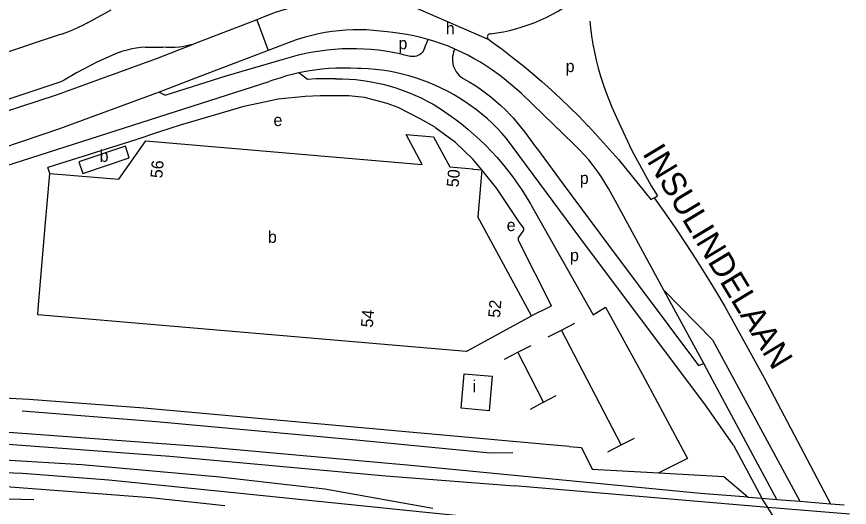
# Model space of a CAD drawing. Extents: x 161494 to 163033, y 383688 to 384862.
# Drawn here: x 162712.5 to 162990.6, y 384018.3 to 384182.1 of the extents above; entities that cross this region are included whole.
import ezdxf

# ---------------------------------------------------------------- set-up
doc = ezdxf.new("R2010")
doc.units = 0
for name, color, linetype in [('BLT_Basislijn', 7, 'Continuous'), ('BLT_Bebouwing', 7, 'Continuous'), ('BLT_Centroide', 7, 'Continuous'), ('BLT_Huisnummer_reeks', 7, 'Continuous'), ('BLT_Spoorlijn', 7, 'Continuous'), ('BLT_Straatnaam_hoofdweg', 7, 'Continuous'), ('BLT_Vlakafsluiter', 7, 'Continuous')]:
    doc.layers.add(name, color=color, linetype=linetype)

msp = doc.modelspace()

# ---------------------------------------------------------------- linework, layer by layer
at = {"layer": 'BLT_Basislijn'}
for p, q in [((162736.15, 384180.03), (162744.08, 384184.32)), ((162792.67, 384181), (162771.29, 384172.75)), ((162727.04, 384176.07), (162682.21, 384161.19)), ((162848.71, 384171.58), (162849.96, 384174.45)), ((162870.21, 384174.43), (162871.16, 384173.7)), ((162755.54, 384171.89), (162761.33, 384171.89)), ((162858.44, 384170.24), (162858.85, 384171.26)), ((162725.87, 384155.94), (162759.59, 384168.21)), ((162841.62, 384169.48), (162843.9, 384168.84)), ((162686.99, 384125.31), (162796.88, 384160.38)), ((162717.96, 384157.23), (162715.59, 384156.44)), ((162760.23, 384143.65), (162752.33, 384140.98)), ((162900.62, 384108.34), (162876.11, 384141.44)), ((162886.41, 384137.8), (162895.04, 384126.21)), ((162723.59, 384129.76), (162722.91, 384131.71)), ((162895.04, 384126.21), (162910.16, 384105.82)), ((162928.62, 384090.76), (162912.35, 384120.67)), ((162924.23, 384121.01), (162925.4, 384121.63)), ((162925.4, 384121.63), (162926.54, 384122.24)), ((162941.97, 384066.24), (162928.62, 384090.76)), ((162894.47, 384077.46), (162898.93, 384079.78)), ((162890, 384075.14), (162894.47, 384077.46)), ((162914.4, 384039.1), (162894.47, 384077.46)), ((162944.9, 384074.22), (162974.05, 384020.29)), ((162875.38, 384067.71), (162879.85, 384070.03)), ((162879.85, 384070.03), (162884.32, 384072.35)), ((162888.49, 384053.4), (162879.85, 384070.03)), ((162944.9, 384060.86), (162941.97, 384066.24)), ((162921.5, 384062.58), (162936.56, 384034.59)), ((162966.31, 384020.93), (162944.9, 384060.86)), ((162962.07, 384061.51), (162984.26, 384019.45)), ((162716.59, 384054.27), (162692.1, 384055.57)), ((162888.49, 384053.4), (162884.03, 384050.89)), ((162888.49, 384053.4), (162892.68, 384055.66)), ((162914.4, 384039.1), (162918.87, 384041.42)), ((162909.93, 384036.78), (162914.4, 384039.1)), ((162951.9, 384039), (162961.39, 384021.34)), ((162936.56, 384034.59), (162926.96, 384029.78)), ((162926.96, 384029.78), (162948.64, 384028.55)), ((162948.64, 384028.55), (162956.78, 384021.72)), ((162956.78, 384021.72), (162961.39, 384021.34)), ((162961.39, 384021.34), (162966.31, 384020.93)), ((162966.31, 384020.93), (162974.05, 384020.29)), ((162974.05, 384020.29), (162984.26, 384019.45)), ((162984.26, 384019.45), (162988.85, 384019.07))]:
    msp.add_line(p, q, dxfattribs=at)
for points in [[(162831.29, 384188.57), (162830.8, 384188.59), (162828.09, 384188.59), (162825.38, 384188.52), (162822.67, 384188.36), (162819.97, 384188.13), (162817.27, 384187.81), (162814.59, 384187.42), (162811.92, 384186.94), (162809.26, 384186.39), (162806.62, 384185.76), (162804, 384185.06), (162801.4, 384184.27), (162798.83, 384183.41), (162796.28, 384182.48), (162793.77, 384181.47), (162792.71, 384181.02)], [(162870.78, 384176.39), (162872.91, 384176.68), (162875.03, 384177.05), (162877.14, 384177.5), (162879.23, 384178.02), (162881.3, 384178.63), (162883.34, 384179.3), (162885.35, 384180.06), (162887.34, 384180.89), (162889.3, 384181.79), (162891.21, 384182.77), (162893.1, 384183.81), (162894.94, 384184.93), (162896.74, 384186.11), (162898.49, 384187.35), (162899.83, 384188.38)], [(162736.15, 384180.03), (162734.54, 384179.14), (162732.88, 384178.32), (162731.2, 384177.56), (162729.48, 384176.89), (162727.73, 384176.28), (162727.04, 384176.07)], [(162792.71, 384181.02), (162792.67, 384181)], [(162903.87, 384180.62), (162904.11, 384178.34), (162904.48, 384175.61), (162904.92, 384172.89), (162905.45, 384170.19), (162906.05, 384167.51), (162906.73, 384164.84), (162907.49, 384162.19), (162908.33, 384159.57), (162909.24, 384156.97), (162910.22, 384154.4), (162911.28, 384151.86), (162912.42, 384149.36), (162912.84, 384148.46)], [(162836.24, 384176.99), (162833.95, 384177.28), (162831.66, 384177.49), (162829.36, 384177.62), (162827.06, 384177.67), (162824.75, 384177.65), (162822.45, 384177.54), (162820.16, 384177.35), (162817.87, 384177.08), (162815.59, 384176.74), (162813.33, 384176.31), (162811.08, 384175.8), (162808.85, 384175.22), (162806.64, 384174.56), (162805.85, 384174.31)], [(162849.96, 384174.45), (162849.85, 384174.49), (162847.53, 384175.11), (162845.19, 384175.65), (162842.84, 384176.11), (162840.47, 384176.5), (162838.09, 384176.8), (162836.24, 384176.99)], [(162870.78, 384176.39), (162870.49, 384176.36), (162870.22, 384176.26), (162869.99, 384176.09), (162869.82, 384175.86), (162869.71, 384175.59), (162869.68, 384175.3), (162869.73, 384175.02), (162869.86, 384174.76), (162870.05, 384174.54), (162870.21, 384174.43)], [(162805.85, 384174.31), (162796.52, 384170.75)], [(162858.85, 384171.26), (162856.67, 384172.17), (162854.42, 384173.02), (162852.15, 384173.79), (162849.96, 384174.45)], [(162871.16, 384173.7), (162874.59, 384171.18), (162877.98, 384168.6), (162881.31, 384165.95), (162884.6, 384163.24), (162887.83, 384160.47), (162891.01, 384157.64), (162894.14, 384154.75), (162897.21, 384151.8), (162900.23, 384148.8), (162903.18, 384145.73), (162903.44, 384145.47)], [(162755.54, 384171.89), (162753.99, 384171.77), (162752.46, 384171.57), (162750.93, 384171.29), (162749.42, 384170.93), (162747.93, 384170.5), (162746.46, 384169.99), (162745.58, 384169.64)], [(162796.47, 384170.74), (162789.5, 384168.08), (162773.74, 384162.08), (162760.16, 384156.84)], [(162771.29, 384172.75), (162769.84, 384172.39), (162768.37, 384172.12), (162766.89, 384171.92), (162765.4, 384171.8), (162763.9, 384171.77), (162762.41, 384171.81), (162761.33, 384171.89)], [(162796.52, 384170.75), (162796.47, 384170.74)], [(162801.93, 384167.98), (162804.27, 384168.68), (162806.63, 384169.3), (162809.01, 384169.85), (162811.41, 384170.32), (162813.82, 384170.71), (162816.24, 384171.02), (162818.67, 384171.25), (162821.11, 384171.4), (162823.55, 384171.47), (162825.99, 384171.46), (162828.43, 384171.37), (162830.86, 384171.2), (162833.29, 384170.95), (162835.71, 384170.62), (162838.12, 384170.22), (162840.51, 384169.73), (162841.62, 384169.48)], [(162848.71, 384171.58), (162848.51, 384171.05), (162848.23, 384170.56), (162847.88, 384170.1), (162847.47, 384169.7), (162847.02, 384169.36), (162846.52, 384169.09), (162845.98, 384168.89), (162845.43, 384168.77), (162844.86, 384168.73), (162844.29, 384168.77), (162843.9, 384168.84)], [(162858.44, 384170.24), (162858.23, 384169.5), (162858.09, 384168.75), (162858.03, 384167.98), (162858.05, 384167.22), (162858.15, 384166.45), (162858.33, 384165.71), (162858.59, 384164.98), (162858.92, 384164.29), (162859.32, 384163.63), (162859.78, 384163.02), (162860.31, 384162.46), (162860.89, 384161.96), (162861.52, 384161.53), (162861.67, 384161.44)], [(162875.26, 384161.33), (162873.36, 384162.8), (162871.42, 384164.21), (162869.43, 384165.56), (162867.4, 384166.83), (162865.33, 384168.04), (162863.21, 384169.18), (162861.07, 384170.25), (162858.85, 384171.26)], [(162745.58, 384169.64), (162739.31, 384166.87), (162732.56, 384163.34), (162728.38, 384160.87), (162727.31, 384160.33), (162717.96, 384157.23)], [(162760.16, 384156.84), (162762.06, 384155.86), (162782.53, 384162.29), (162801.93, 384167.98)], [(162826.31, 384164.8), (162823.92, 384164.9), (162821.53, 384164.93), (162819.14, 384164.88), (162816.76, 384164.74), (162814.37, 384164.53), (162812, 384164.23), (162809.64, 384163.86), (162807.29, 384163.41), (162806.69, 384163.27)], [(162876.11, 384141.44), (162874.58, 384143.17), (162872.99, 384144.85), (162871.34, 384146.47), (162869.64, 384148.03), (162867.89, 384149.53), (162866.08, 384150.97), (162864.23, 384152.35), (162862.33, 384153.66), (162860.38, 384154.9), (162858.4, 384156.08), (162856.37, 384157.19), (162854.31, 384158.22), (162852.21, 384159.19), (162850.08, 384160.08), (162847.92, 384160.9), (162845.73, 384161.64), (162843.52, 384162.3), (162841.29, 384162.89), (162839.04, 384163.4), (162836.77, 384163.83), (162834.49, 384164.19), (162832.19, 384164.46), (162829.89, 384164.66), (162827.59, 384164.77), (162826.31, 384164.8)], [(162806.69, 384163.27), (162804.96, 384162.88), (162802.65, 384162.27), (162800.36, 384161.59), (162798.09, 384160.83), (162796.88, 384160.38)], [(162819.02, 384161.37), (162812.44, 384161.35), (162809.65, 384161.13), (162806.69, 384163.27)], [(162819.02, 384161.37), (162821.29, 384161.35), (162823.56, 384161.24), (162825.82, 384161.06), (162828.07, 384160.79), (162830.31, 384160.45), (162832.54, 384160.03), (162834.76, 384159.53), (162836.95, 384158.95), (162839.12, 384158.3), (162841.27, 384157.57), (162843.39, 384156.76), (162845.49, 384155.88), (162847.54, 384154.93), (162849.57, 384153.9), (162851.56, 384152.81), (162853.5, 384151.64), (162854.38, 384151.08)], [(162861.67, 384161.44), (162863.6, 384160.34), (162865.48, 384159.18), (162867.33, 384157.95), (162869.12, 384156.66), (162870.87, 384155.3), (162872.57, 384153.88), (162874.22, 384152.4), (162875.81, 384150.86), (162877.34, 384149.26), (162878.26, 384148.25)], [(162898.57, 384139.54), (162888.34, 384149.42), (162880.94, 384156.5), (162875.26, 384161.33)], [(162715.59, 384156.44), (162687.56, 384147.15), (162682.63, 384142.96)], [(162760.16, 384156.84), (162726.82, 384144.61), (162688.65, 384131.73)], [(162867.84, 384130.92), (162867.27, 384131.62), (162864.82, 384134.51), (162859, 384140.05), (162852.51, 384144.86), (162852.03, 384145.24), (162847.27, 384147.95), (162839.9, 384151.78), (162836.27, 384153.08), (162828.7, 384155.04), (162823.44, 384155.6), (162813.84, 384155.63), (162808.83, 384155.38), (162799.89, 384154.49), (162795.23, 384153.54), (162788.34, 384152.1), (162767.17, 384145.89), (162760.23, 384143.65)], [(162854.38, 384151.08), (162856.64, 384149.55), (162858.86, 384147.95), (162861.03, 384146.29), (162863.15, 384144.57), (162865.21, 384142.78), (162867.23, 384140.94), (162869.18, 384139.03), (162871.09, 384137.07), (162872.93, 384135.06), (162874.71, 384132.99), (162876.43, 384130.87), (162878.1, 384128.7), (162879.69, 384126.49), (162881.22, 384124.22), (162882.68, 384121.92), (162884.08, 384119.57), (162884.29, 384119.2)], [(162878.26, 384148.25), (162880.24, 384145.92), (162882.17, 384143.55), (162884.02, 384141.12), (162885.82, 384138.65), (162886.41, 384137.8)], [(162912.84, 384148.46), (162917.97, 384137.34), (162924.38, 384125.58), (162926.54, 384122.24)], [(162903.44, 384145.47), (162913.48, 384134.35), (162924.23, 384121.01)], [(162752.33, 384140.98), (162722.91, 384131.71)], [(162912.35, 384120.67), (162911.29, 384122.73), (162910.17, 384124.76), (162908.97, 384126.74), (162907.71, 384128.68), (162906.38, 384130.58), (162904.99, 384132.43), (162903.53, 384134.23), (162902.02, 384135.98), (162900.44, 384137.67), (162898.8, 384139.32), (162898.57, 384139.54)], [(162891.13, 384085.57), (162880.1, 384107.36), (162880.04, 384108.25), (162881.92, 384110.8), (162881.92, 384111.49), (162880.42, 384113.34), (162872.85, 384124.72), (162867.84, 384130.92)], [(162925.4, 384121.63), (162928.97, 384116.56), (162932.48, 384111.45), (162935.93, 384106.28), (162939.31, 384101.08), (162942.62, 384095.83), (162945.86, 384090.54), (162948.97, 384085.3)], [(162884.29, 384119.2), (162904.99, 384082.54), (162909.18, 384085.08), (162921.5, 384062.58)], [(162951.9, 384039), (162942.86, 384051.91), (162900.62, 384108.34)], [(162910.16, 384105.82), (162940.18, 384065.64), (162941.97, 384066.24)], [(162891.13, 384085.57), (162890.3, 384085.14), (162884.46, 384082.15)], [(162896.99, 384038.57), (162888.11, 384039.33), (162754.96, 384051.37), (162716.59, 384054.27)], [(162714.37, 384050.52), (162759.19, 384046.91), (162823.65, 384041.08), (162870.58, 384036.51), (162878.21, 384036.64)], [(162956.78, 384021.72), (162940.81, 384022.86), (162844.13, 384032.25), (162776, 384038.39), (162705.31, 384043.59), (162655, 384044.9), (162627.45, 384044.8), (162579.26, 384042.49), (162510.26, 384034.87), (162452.51, 384024.7), (162377.46, 384008.85), (162301.58, 383991.65), (162233.15, 383976.81), (162161.35, 383961.08), (162082.65, 383946.35), (162000.1, 383931.74), (161945.86, 383921.22), (161938.95, 383921.37)], [(162896.99, 384038.57), (162901.17, 384038.23), (162904.71, 384031.03), (162926.96, 384029.78)]]:
    msp.add_lwpolyline(points, dxfattribs=at)
at = {"layer": 'BLT_Bebouwing'}
for p, q in [((162867.84, 384130.92), (162866.49, 384115.28)), ((162884.46, 384082.15), (162866.49, 384115.28)), ((162719.73, 384084.49), (162721.96, 384110.67)), ((162721.96, 384110.67), (162721.98, 384110.83)), ((162862.66, 384070.33), (162884.46, 384082.15))]:
    msp.add_line(p, q, dxfattribs=at)
for points in [[(162847.98, 384132.77), (162842.56, 384142.77), (162851.76, 384141.95), (162857.16, 384131.99)], [(162723.59, 384129.76), (162746.68, 384127.79), (162755.64, 384140.64), (162847.98, 384132.77)], [(162857.16, 384131.99), (162864.81, 384131.33), (162864.79, 384131.16), (162867.84, 384130.92)], [(162721.98, 384110.83), (162723.59, 384129.76)], [(162862.66, 384070.33), (162719.56, 384082.53), (162719.73, 384084.49)], [(162870.34, 384050.5), (162860.9, 384051.33), (162861.92, 384062.89), (162871.35, 384062.06), (162870.34, 384050.5)]]:
    msp.add_lwpolyline(points, dxfattribs=at)
msp.add_lwpolyline([(162748.82, 384138.87), (162733.27, 384133.61), (162734.58, 384129.73), (162750.13, 384134.99)], close=True, dxfattribs=at)
at = {"layer": 'BLT_Spoorlijn'}
for points in [[(162670.1, 384040.71), (162709.74, 384039.34), (162763.63, 384035.31), (162835.76, 384028.79), (162878.78, 384025.43)], [(162851.52, 384017.92), (162815.39, 384024.3), (162780.35, 384028.34), (162734.32, 384032.49), (162682.28, 384035.6), (162657.55, 384036.07), (162644.62, 384036.06), (162620.91, 384035.6), (162600, 384034.57), (162572.62, 384033.21), (162544.84, 384030.9), (162520.54, 384027.83), (162490.18, 384023.26), (162444.69, 384014.9), (162206.08, 383962.22), (162182.09, 383956.51), (162143.86, 383951.57)], [(162900.86, 384011.36), (162871.5, 384014.34), (162849.2, 384016.61), (162786.11, 384023.02), (162743.32, 384027.37), (162714.49, 384029.62), (162675.59, 384031.05), (162617.43, 384030.81), (162571.29, 384028.11), (162530.64, 384023.81), (162498.89, 384019.36), (162460.78, 384012.83), (162360.78, 383991.35), (162187.34, 383952.61), (162103.09, 383933.78), (162003.41, 383912.03), (161897.47, 383888.44), (161858.44, 383879.75), (161796.71, 383866.01)], [(162015.34, 383899.38), (162017.25, 383899.68), (162080.65, 383914.34), (162260.47, 383954.06), (162264.14, 383955.18), (162275.03, 383957.62), (162500.2, 384007.1), (162541.18, 384015.46), (162562.76, 384019.37), (162588.28, 384023.03), (162600, 384024.15), (162615.59, 384025.65), (162626.19, 384026.21), (162676.14, 384026.61), (162705.93, 384025.41), (162732.39, 384023.5), (162757.2, 384021.52), (162782.07, 384018.89)], [(162963.3, 384018.28), (162878.78, 384025.43)], [(162718.29, 384020.75), (162713.88, 384020.92), (162695.07, 384020.96), (162676.79, 384020.24), (162656.02, 384019.05), (162600, 384013.9), (162494.64, 384004.23)], [(162990.56, 384015.97), (162963.3, 384018.28)]]:
    msp.add_lwpolyline(points, dxfattribs=at)
at = {"layer": 'BLT_Vlakafsluiter'}
for p, q in [((162838.93, 384188.09), (162870.21, 384174.43)), ((162792.67, 384181), (162796.47, 384170.74)), ((162792.71, 384181.02), (162796.52, 384170.75)), ((162759.59, 384168.21), (162771.29, 384172.75)), ((162928.62, 384090.76), (162944.9, 384074.22)), ((162948.97, 384085.3), (162962.07, 384061.51)), ((162963.3, 384018.28), (162961.39, 384021.34)), ((162973.07, 384002.59), (162963.3, 384018.28))]:
    msp.add_line(p, q, dxfattribs=at)
msp.add_lwpolyline([(162684.25, 384142.42), (162725.87, 384155.94)], dxfattribs=at)

# ---------------------------------------------------------------- texts
at = {"layer": 'BLT_Centroide'}
for s, p in [('h', (162855.8, 384176.15)), ('p', (162840.01, 384171.18)), ('p', (162895.84, 384163.56)), ('e', (162798.27, 384145.56)), ('b', (162740.23, 384133.59)), ('p', (162900.55, 384126.2)), ('e', (162876.15, 384110.5)), ('b', (162796.42, 384106.56)), ('p', (162897.29, 384100.45)), ('i', (162864.79, 384056.7))]:
    msp.add_text(s, height=4, dxfattribs=at).set_placement(p)
at = {"layer": 'BLT_Huisnummer_reeks'}
for s, p in [('56', (162761.15, 384128.03)), ('50', (162860.06, 384125.01)), ('52', (162873.9, 384081.43)), ('54', (162831.43, 384078.18))]:
    msp.add_text(s, height=4, rotation=85.0696, dxfattribs=at).set_placement(p)
at = {"layer": 'BLT_Straatnaam_hoofdweg'}
msp.add_text('INSULINDELAAN', height=8, rotation=301.1453, dxfattribs=at).set_placement((162921.27, 384136.43))

doc.saveas('drawing.dxf')
